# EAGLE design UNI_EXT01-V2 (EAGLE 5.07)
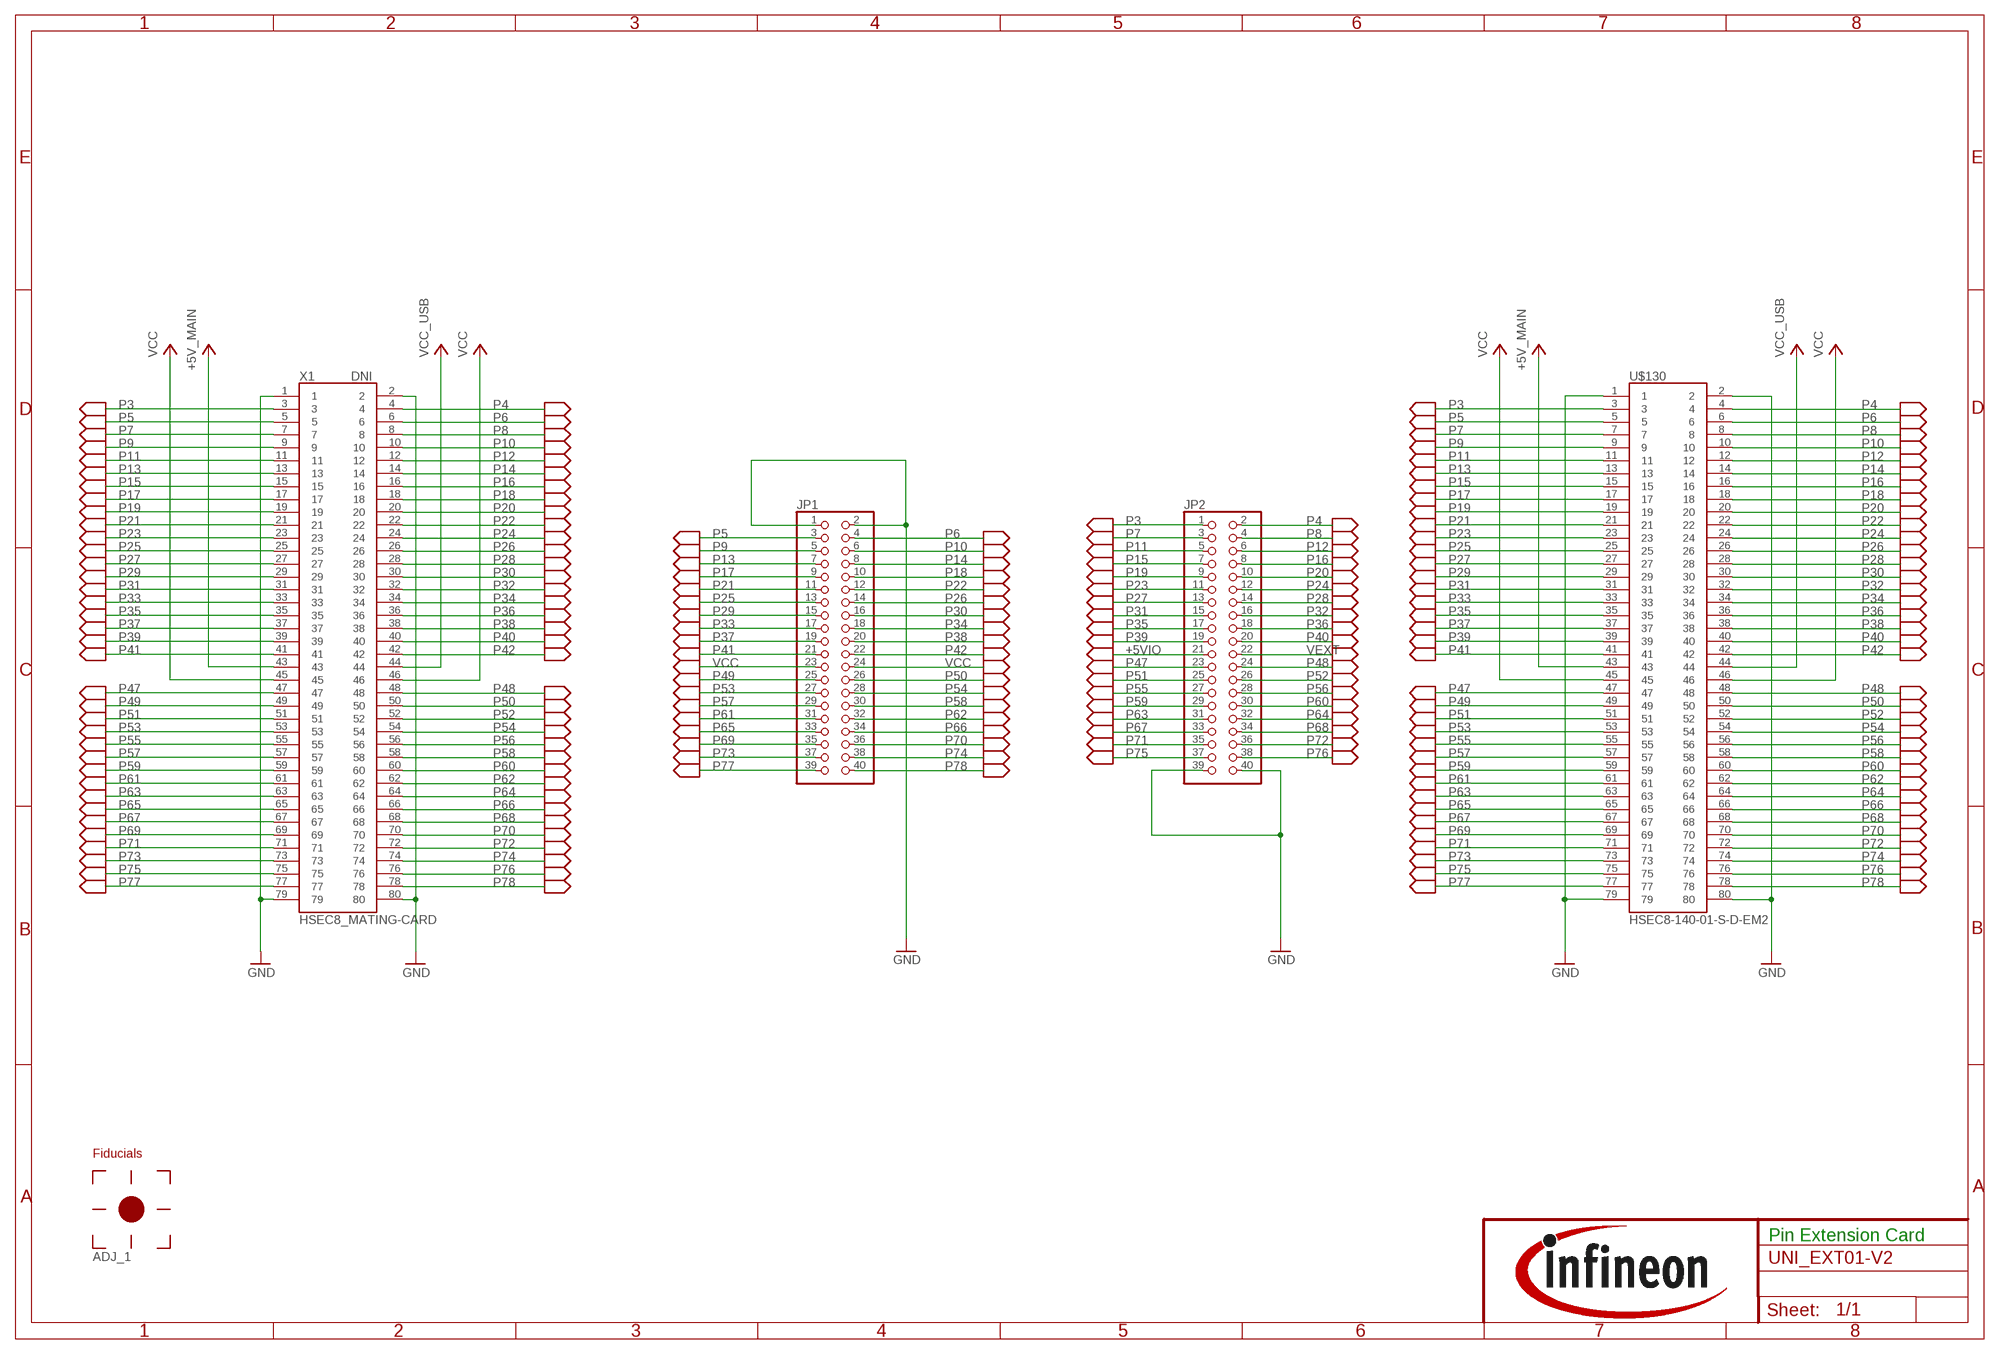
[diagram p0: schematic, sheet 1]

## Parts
ADJ_1  FIDUCIAL  [FIDUCIAL]
JP1  PINHD-2X20  [2X20]
JP2  PINHD-2X20  [2X20]
U$130  HSEC8-140-01-S-D-EM2  [HSEC8-140-01-XX-D-EM2]
X1  HSEC8_MATING-CARD  [HSEC8_MATING-CARD_80]

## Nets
+5VIO: JP2.21 U$130.43 X1.43 ; supply symbol labelled +5V_MAIN
GND: JP1.1 JP1.2 JP2.39 JP2.40 U$130.1 U$130.2 U$130.79 U$130.80 X1.1 X1.2 X1.79 X1.80
P3: JP2.1 U$130.3 X1.3
P4: JP2.2 U$130.4 X1.4
P5: JP1.3 U$130.5 X1.5
P6: JP1.4 U$130.6 X1.6
P7: JP2.3 U$130.7 X1.7
P8: JP2.4 U$130.8 X1.8
P9: JP1.5 U$130.9 X1.9
P10: JP1.6 U$130.10 X1.10
P11: JP2.5 U$130.11 X1.11
P12: JP2.6 U$130.12 X1.12
P13: JP1.7 U$130.13 X1.13
P14: JP1.8 U$130.14 X1.14
P15: JP2.7 U$130.15 X1.15
P16: JP2.8 U$130.16 X1.16
P17: JP1.9 U$130.17 X1.17
P18: JP1.10 U$130.18 X1.18
P19: JP2.9 U$130.19 X1.19
P20: JP2.10 U$130.20 X1.20
P21: JP1.11 U$130.21 X1.21
P22: JP1.12 U$130.22 X1.22
P23: JP2.11 U$130.23 X1.23
P24: JP2.12 U$130.24 X1.24
P25: JP1.13 U$130.25 X1.25
P26: JP1.14 U$130.26 X1.26
P27: JP2.13 U$130.27 X1.27
P28: JP2.14 U$130.28 X1.28
P29: JP1.15 U$130.29 X1.29
P30: JP1.16 U$130.30 X1.30
P31: JP2.15 U$130.31 X1.31
P32: JP2.16 U$130.32 X1.32
P33: JP1.17 U$130.33 X1.33
P34: JP1.18 U$130.34 X1.34
P35: JP2.17 U$130.35 X1.35
P36: JP2.18 U$130.36 X1.36
P37: JP1.19 U$130.37 X1.37
P38: JP1.20 U$130.38 X1.38
P39: JP2.19 U$130.39 X1.39
P40: JP2.20 U$130.40 X1.40
P41: JP1.21 U$130.41 X1.41
P42: JP1.22 U$130.42 X1.42
P47: JP2.23 U$130.47 X1.47
P48: JP2.24 U$130.48 X1.48
P49: JP1.25 U$130.49 X1.49
P50: JP1.26 U$130.50 X1.50
P51: JP2.25 U$130.51 X1.51
P52: JP2.26 U$130.52 X1.52
P53: JP1.27 U$130.53 X1.53
P54: JP1.28 U$130.54 X1.54
P55: JP2.27 U$130.55 X1.55
P56: JP2.28 U$130.56 X1.56
P57: JP1.29 U$130.57 X1.57
P58: JP1.30 U$130.58 X1.58
P59: JP2.29 U$130.59 X1.59
P60: JP2.30 U$130.60 X1.60
P61: JP1.31 U$130.61 X1.61
P62: JP1.32 U$130.62 X1.62
P63: JP2.31 U$130.63 X1.63
P64: JP2.32 U$130.64 X1.64
P65: JP1.33 U$130.65 X1.65
P66: JP1.34 U$130.66 X1.66
P67: JP2.33 U$130.67 X1.67
P68: JP2.34 U$130.68 X1.68
P69: JP1.35 U$130.69 X1.69
P70: JP1.36 U$130.70 X1.70
P71: JP2.35 U$130.71 X1.71
P72: JP2.36 U$130.72 X1.72
P73: JP1.37 U$130.73 X1.73
P74: JP1.38 U$130.74 X1.74
P75: JP2.37 U$130.75 X1.75
P76: JP2.38 U$130.76 X1.76
P77: JP1.39 U$130.77 X1.77
P78: JP1.40 U$130.78 X1.78
VCC: JP1.23 JP1.24 U$130.45 U$130.46 X1.45 X1.46
VEXT: JP2.22 U$130.44 X1.44 ; supply symbol labelled VCC_USB

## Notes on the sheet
- DNI
- Fiducials
- Pin Extension Card

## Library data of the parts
ADJ_1 = Global:FIDUCIAL: Fiducial
JP1 JP2 = pinhead:PINHD-2X20: PIN HEADER
U$130 = _HSEC8-140-01-XX-D-EM2:HSEC8-140-01-S-D-EM2
X1 = _XSE080:HSEC8_MATING-CARD

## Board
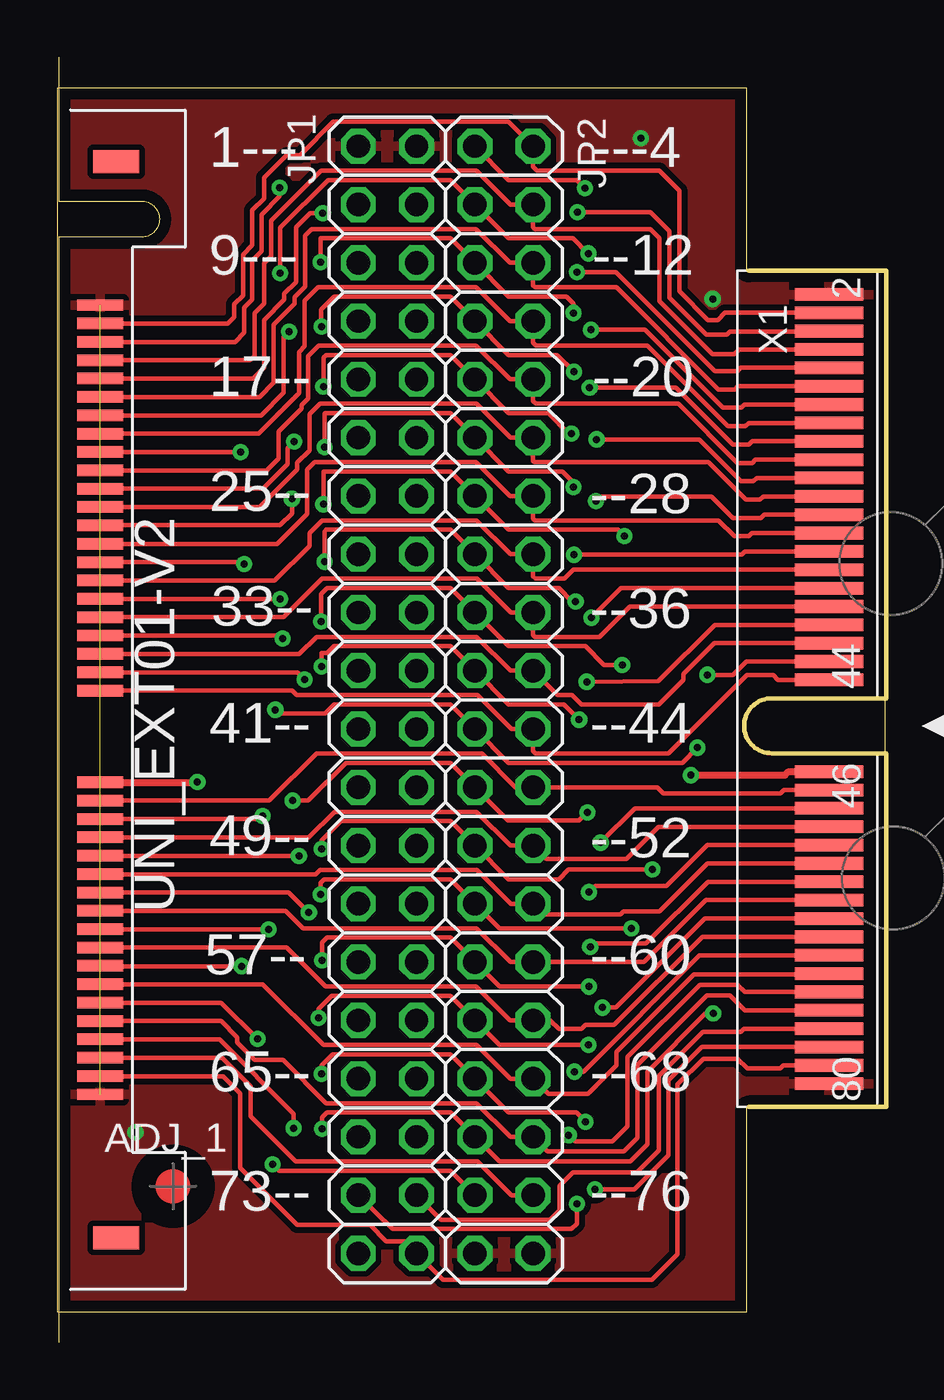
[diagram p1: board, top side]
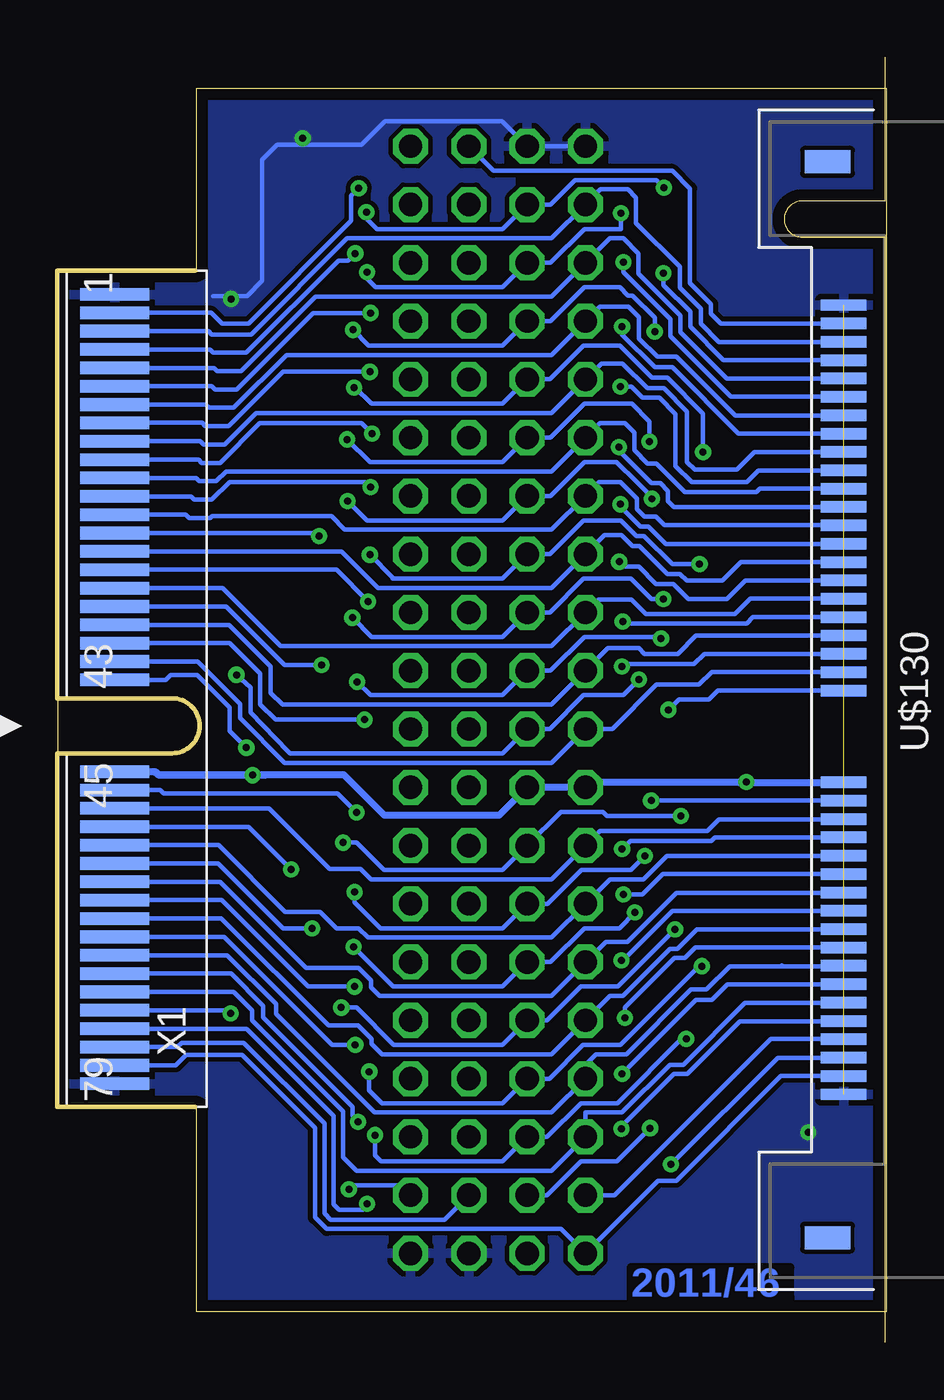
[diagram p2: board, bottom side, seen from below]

Size 36.14 x 56 mm. Coordinates in mm from the lower left corner, seen from the top.
Outline: 0,1.32 30.06,1.32 30.06,10.21 36.1,10.19 36.1,46.69 30.06,46.71 30.06,54.66 0,54.66 0,1.32
Copper layers (1+2*15+16): Top 0.035mm / dielectric 0.5mm / Route2 0.035mm / dielectric 0.5mm / Route15 0.035mm / dielectric 0.5mm / Bottom 0.035mm
Design rules "TESTCPU_01-A1 *": minimum track width 0.2mm, minimum drill 0.2mm, track to track 0.2mm, track to pad 0.2mm, pad to pad 0.15mm, via to via 0.2mm, smd to smd 0.2mm, copper to edge 0.5mm, drill to drill 0.5mm, minimum pad ring 10mil, minimum via ring 0.2mm, stop-mask expansion 4mil, vias tented up to drill 0.34mm, thermal gap 10mil

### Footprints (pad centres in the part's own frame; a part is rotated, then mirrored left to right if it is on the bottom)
2X20 = drill 1.016 octagon: 1 -24.13,-1.27; 2 -24.13,1.27; 3 -21.59,-1.27; 4 -21.59,1.27; 5 -19.05,-1.27; 6 -19.05,1.27; 7 -16.51,-1.27; 8 -16.51,1.27; 9 -13.97,-1.27; 10 -13.97,1.27; 11 -11.43,-1.27; 12 -11.43,1.27; 13 -8.89,-1.27; 14 -8.89,1.27; 15 -6.35,-1.27; 16 -6.35,1.27; 17 -3.81,-1.27; 18 -3.81,1.27; 19 -1.27,-1.27; 20 -1.27,1.27; 21 1.27,-1.27; 22 1.27,1.27; 23 3.81,-1.27; 24 3.81,1.27; 25 6.35,-1.27; 26 6.35,1.27; 27 8.89,-1.27; 28 8.89,1.27; 29 11.43,-1.27; 30 11.43,1.27; 31 13.97,-1.27; 32 13.97,1.27; 33 16.51,-1.27; 34 16.51,1.27; 35 19.05,-1.27; 36 19.05,1.27; 37 21.59,-1.27; 38 21.59,1.27; 39 24.13,-1.27; 40 24.13,1.27
HSEC8-140-01-XX-D-EM2 = smd 0.5 x 2: 1 -17.2,-1.8; 3 -16.4,-1.8; 5 -15.6,-1.8; 7 -14.8,-1.8; 9 -14,-1.8; 11 -13.2,-1.8; 13 -12.4,-1.8; 15 -11.6,-1.8; 17 -10.8,-1.8; 19 -10,-1.8; 21 -9.2,-1.8; 23 -8.4,-1.8; 25 -7.6,-1.8; 27 -6.8,-1.8; 29 -6,-1.8; 31 -5.2,-1.8; 33 -4.4,-1.8; 35 -3.6,-1.8; 37 -2.8,-1.8; 39 -2,-1.8; 41 -1.2,-1.8; 43 -0.4,-1.8; 45 3.6,-1.8; 47 4.4,-1.8; 49 5.2,-1.8; 51 6,-1.8; 53 6.8,-1.8; 55 7.6,-1.8; 57 8.4,-1.8; 59 9.2,-1.8; 61 10,-1.8; 63 10.8,-1.8; 65 11.6,-1.8; 67 12.4,-1.8; 69 13.2,-1.8; 71 14,-1.8; 73 14.8,-1.8; 75 15.6,-1.8; 77 16.4,-1.8; 79 17.2,-1.8 | smd 0.5 x 2 bottom: 2 -17.2,-1.8; 4 -16.4,-1.8; 6 -15.6,-1.8; 8 -14.8,-1.8; 10 -14,-1.8; 12 -13.2,-1.8; 14 -12.4,-1.8; 16 -11.6,-1.8; 18 -10.8,-1.8; 20 -10,-1.8; 22 -9.2,-1.8; 24 -8.4,-1.8; 26 -7.6,-1.8; 28 -6.8,-1.8; 30 -6,-1.8; 32 -5.2,-1.8; 34 -4.4,-1.8; 36 -3.6,-1.8; 38 -2.8,-1.8; 40 -2,-1.8; 42 -1.2,-1.8; 44 -0.4,-1.8; 46 3.6,-1.8; 48 4.4,-1.8; 50 5.2,-1.8; 52 6,-1.8; 54 6.8,-1.8; 56 7.6,-1.8; 58 8.4,-1.8; 60 9.2,-1.8; 62 10,-1.8; 64 10.8,-1.8; 66 11.6,-1.8; 68 12.4,-1.8; 70 13.2,-1.8; 72 14,-1.8; 74 14.8,-1.8; 76 15.6,-1.8; 78 16.4,-1.8; 80 17.2,-1.8 | smd 1 x 2: 81 -23.45,-2.5; 82 23.45,-2.5 | smd 1 x 2 bottom: 83 -23.45,-2.5; 84 23.45,-2.5
HSEC8_MATING-CARD_80 = smd 0.55 x 3 bottom: 1 -18.8,-2.5; 3 -18,-2.5; 5 -17.2,-2.5; 7 -16.4,-2.5; 9 -15.6,-2.5; 11 -14.8,-2.5; 13 -14,-2.5; 15 -13.2,-2.5; 17 -12.4,-2.5; 19 -11.6,-2.5; 21 -10.8,-2.5; 23 -10,-2.5; 25 -9.2,-2.5; 27 -8.4,-2.5; 29 -7.6,-2.5; 31 -6.8,-2.5; 33 -6,-2.5; 35 -5.2,-2.5; 37 -4.4,-2.5; 39 -3.6,-2.5; 41 -2.8,-2.5; 43 -2,-2.5; 45 2,-2.5; 47 2.8,-2.5; 49 3.6,-2.5; 51 4.4,-2.5; 53 5.2,-2.5; 55 6,-2.5; 57 6.8,-2.5; 59 7.6,-2.5; 61 8.4,-2.5; 63 9.2,-2.5; 65 10,-2.5; 67 10.8,-2.5; 69 11.6,-2.5; 71 12.4,-2.5; 73 13.2,-2.5; 75 14,-2.5; 77 14.8,-2.5; 79 15.6,-2.5 | smd 0.55 x 3: 2 -18.8,-2.5; 4 -18,-2.5; 6 -17.2,-2.5; 8 -16.4,-2.5; 10 -15.6,-2.5; 12 -14.8,-2.5; 14 -14,-2.5; 16 -13.2,-2.5; 18 -12.4,-2.5; 20 -11.6,-2.5; 22 -10.8,-2.5; 24 -10,-2.5; 26 -9.2,-2.5; 28 -8.4,-2.5; 30 -7.6,-2.5; 32 -6.8,-2.5; 34 -6,-2.5; 36 -5.2,-2.5; 38 -4.4,-2.5; 40 -3.6,-2.5; 42 -2.8,-2.5; 44 -2,-2.5; 46 2,-2.5; 48 2.8,-2.5; 50 3.6,-2.5; 52 4.4,-2.5; 54 5.2,-2.5; 56 6,-2.5; 58 6.8,-2.5; 60 7.6,-2.5; 62 8.4,-2.5; 64 9.2,-2.5; 66 10,-2.5; 68 10.8,-2.5; 70 11.6,-2.5; 72 12.4,-2.5; 74 13.2,-2.5; 76 14,-2.5; 78 14.8,-2.5; 80 15.6,-2.5

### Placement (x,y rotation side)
ADJ_1  5.05,6.79 0 top
JP1  14.39,27.99 270 top
JP2  19.47,27.99 270 top
U$130  0.06,28 270 bottom
X1  36.14,26.86 270 top

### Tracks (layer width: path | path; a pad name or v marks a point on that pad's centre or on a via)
+5VIO  (via drill 0.3)
  Top 0.203: v27.9,25.91 27.24,25.25 19.67,25.25 JP2.21 17.13,27.79 12.05,27.79 11.67,27.41 9.65,27.41 v9.5,27.56
  Bottom 0.203: v27.9,25.91 28.64,26.65 28.64,27.66 30.05,29.07 31.21,29.07 31.42,28.86 X1.43 | v9.5,27.56 9.05,28.02 7.73,28.02 7.35,28.4 U$130.43
GND  (via drill 0.3)  (1 unrouted)
  Bottom 0.203: JP1.1 JP1.2 16.75,53.22 21.86,53.22 22.87,52.2 26.56,52.2 27.22,51.54 27.22,46.26 27.88,45.6 29.35,45.6
  other vias: 25.44,52.48 28.57,45.47 3.4,9.14
  pour Bottom: 0.31,54.66 30.06,54.66 30.06,47.04 35.98,47.04 35.98,10.21 29.96,10.11 29.96,1.22 0.31,1.32
  pour Top (isolate 0.254): 0.51,54.61 29.93,54.71 29.93,46.69 35.9,46.59 35.9,10.21 30.05,9.81 30.05,1.18 0.51,1.58
P3  (via drill 0.3)
  Top 0.203: JP2.1 19.67,50.65 22.64,50.65 v23,50.3
  Bottom 0.203: JP2.1 17.13,51.06 9.33,51.06 8.56,50.28 8.56,46.16 7.64,45.25 7.64,44.83 7.21,44.4 U$130.3 | v23,50.3 23.33,49.97 23.33,48.87 27.8,44.4 28.97,44.4 29.43,44.86 X1.3
P4
  Top 0.203: X1.4 29.1,44.86 28.79,44.56 28.36,44.56 27.11,45.8 27.11,50.19 26.25,51.06 20.92,51.06 20.74,51.24 JP2.2 19.67,53.19 12.03,53.19 10.58,51.74 10,51.74 9.01,50.75 9.01,49.84 8.5,49.33 8.5,47.81 8.09,47.4 8.09,45.62 7.71,45.24 7.71,44.68 7.42,44.39 U$130.4
  Top 0.254: U$130.4
P5
  Bottom 0.203: X1.5 29.55,44.07 29.4,43.92 27.7,43.92 23.51,48.11 14.59,48.11 JP1.3 12.46,50.24 11.27,50.24 10.91,49.89 10.91,48.77 9.01,46.87 9.01,45.95 8.09,45.04 8.1,45.03 8.1,44.39 7.29,43.59 1.87,43.59 U$130.5
P6  (via drill 0.3)
  Top 0.203: v9.69,50.32 9.69,49.94 8.9,49.15 8.9,47.55 8.5,47.15 8.5,45.44 8.14,45.09 8.14,44 7.74,43.59 U$130.6 | v22.67,49.25 25.84,49.25 26.68,48.42 26.68,45.52 28.28,43.92 29.18,43.92 29.31,44.05 X1.6
  Bottom 0.203: v9.69,50.32 10.02,50.65 13.58,50.65 14.64,49.58 JP1.4 16.73,48.52 22.21,48.52 22.67,48.97 v22.67,49.25
P7  (via drill 0.3)
  Top 0.203: v9.72,46.59 9.72,48.57 11.8,50.65 17.13,50.65 JP2.3 19.67,48.11 22.47,48.11 23.13,47.45 v23.15,47.45
  Bottom 0.203: v9.72,46.59 9.72,46.08 8.55,44.91 8.55,44.25 7.09,42.8 U$130.7 | v23.15,47.45 23.46,47.15 23.89,47.15 27.91,43.12 29.35,43.12 29.49,43.26 X1.7 | X1.7
P8
  Top 0.203: X1.8 29.72,43.27 29.51,43.06 28.56,43.06 26.25,45.37 26.25,48.11 25.84,48.52 20.82,48.52 20.74,48.59 JP2.4 19.75,49.58 18.28,51.06 11.49,51.06 9.31,48.87 9.31,47.32 9.01,47.02 9.01,45.27 8.6,44.86 8.6,42.98 8.41,42.79 U$130.8
P9
  Bottom 0.203: X1.9 29.3,42.46 29.17,42.32 28.13,42.32 24.88,45.57 14.59,45.57 JP1.5 12.05,48.11 11.47,48.11 10.81,47.45 10.81,46.56 8.98,44.73 8.99,44.73 8.99,44.02 6.95,41.99 1.87,41.99 U$130.9
P10  (via drill 0.3)
  Top 0.203: v11.57,49.2 11.01,49.2 10.4,48.59 10.4,46.21 9.89,45.7 9.89,45.44 9.01,44.56 9.01,42.47 8.53,41.99 U$130.10 | v22.64,46.64 24.35,46.64 28.66,42.32 29.64,42.32 29.79,42.47 X1.10
  Bottom 0.203: v11.57,49.2 11.57,48.52 13.17,48.52 14.64,47.04 JP1.6 16.73,45.98 22.26,45.98 22.64,46.36 v22.64,46.64
P11  (via drill 0.3)
  Top 0.203: v11.47,47.07 11.47,48.11 17.13,48.11 JP2.5 19.67,45.57 22.19,45.57 22.49,45.27 v22.49,44.86
  Bottom 0.203: v11.47,47.07 11.47,46.64 9.41,44.58 9.41,43.84 6.78,41.21 1.88,41.21 U$130.11 | v22.49,44.86 24.98,44.86 28.32,41.52 29.27,41.52 29.41,41.67 X1.11
P12
  Top 0.203: X1.12 29.67,41.66 29.53,41.52 28.82,41.52 24.37,45.98 20.82,45.98 20.74,46.05 JP2.6 19.72,47.04 18.25,48.52 11.09,48.52 10.81,48.24 10.81,46 10.35,45.55 10.35,45.27 9.44,44.35 9.44,41.81 8.82,41.19 U$130.12
P13
  Bottom 0.203: X1.13 29.67,40.86 29.53,40.72 28.46,40.72 26.15,43.03 14.59,43.03 JP1.7 12.49,45.14 11.24,45.14 10.78,44.68 10.78,43.75 9.98,42.95 9.15,42.95 6.59,40.39 1.87,40.39 U$130.13
P14  (via drill 0.3)
  Top 0.203: v10.1,44.05 9.87,43.82 9.87,41.38 8.88,40.39 U$130.14 | v23.25,44.12 25.62,44.12 29.02,40.72 29.82,40.72 29.96,40.86 X1.14
  Bottom 0.203: v10.1,44.05 10.1,44.66 11.06,45.62 11.27,45.62 11.62,45.98 13.17,45.98 14.64,44.5 JP1.8 16.73,43.44 22.57,43.44 v23.25,44.12
P15  (via drill 0.3)
  Top 0.203: v22.52,42.29 21.78,43.03 19.67,43.03 JP2.7 17.13,45.57 12.05,45.57 11.49,45.01 11.49,44.29 v11.52,44.27
  Bottom 0.203: v22.52,42.29 26.3,42.29 28.67,39.92 29.69,39.92 29.84,40.07 X1.15 | v11.52,44.27 11.52,43.92 10.09,42.49 9.33,42.49 6.44,39.6 U$130.15
P16
  Top 0.203: X1.16 30.14,40.06 30,39.92 29.23,39.92 25.72,43.44 20.87,43.44 20.74,43.56 JP2.8 19.72,44.5 18.25,45.98 11.37,45.98 10.78,45.39 10.78,43.41 10.53,43.16 10.53,41.35 8.77,39.59 U$130.16
P17
  Bottom 0.203: X1.17 29.91,39.26 29.77,39.12 28.84,39.12 27.47,40.49 14.59,40.49 JP1.9 12.43,42.66 11.51,42.66 10.43,41.57 9.7,41.57 8.69,40.56 8.69,38.37 8.35,38.03 6.52,38.03 5.75,38.8 2.63,38.8 2.59,38.77 1.9,38.77 U$130.17
P18  (via drill 0.3)
  Top 0.203: v7.98,38.79 v7.99,38.79 1.86,38.79 U$130.18 | v23.2,41.61 26.96,41.61 29.45,39.12 30.15,39.12 30.29,39.26 X1.18
  Bottom 0.203: v23.2,41.61 23.15,41.61 22.44,40.9 16.73,40.9 JP1.10 14.67,41.96 13.2,43.44 11.62,43.44 10.22,42.04 9.55,42.04 7.99,40.48 v7.99,38.79
P19  (via drill 0.3)
  Top 0.203: v11.6,41.64 11.6,42.9 11.72,43.03 17.13,43.03 JP2.9 19.67,40.49 21.4,40.49 22.29,39.6 v22.42,39.6
  Bottom 0.203: v22.42,39.6 22.87,40.06 27.32,40.06 29.05,38.32 29.85,38.32 29.99,38.46 X1.19 | v11.6,41.64 11.11,41.64 10.63,41.16 9.9,41.16 9.19,40.45 9.19,38.19 8.48,37.48 6.09,37.48 5.57,37.99 U$130.19
P20
  Top 0.203: X1.20 30.43,38.46 30.29,38.32 29.64,38.32 27.06,40.9 20.87,40.9 20.74,41.02 JP2.10 19.72,41.96 18.25,43.44 11.39,43.44 10.94,42.98 10.94,41.13 10.66,40.85 10.66,40.69 9.64,39.68 9.64,38.51 9.12,37.99 U$130.20
P21
  Bottom 0.203: X1.21 30.09,37.67 29.95,37.52 29.22,37.52 28.79,37.95 14.59,37.95 JP1.11 12.48,40.06 11.4,40.06 10.99,39.65 10.99,38.87 10.41,38.29 10.01,38.29 8.78,37.06 5.66,37.06 5.52,37.2 U$130.21
P22  (via drill 0.3)
  Top 0.203: v10.33,39.25 10.05,38.97 10.05,38.28 8.96,37.19 U$130.22 | v23.51,39.35 27.98,39.35 29.8,37.52 30.35,37.52 30.49,37.67 X1.22
  Bottom 0.203: v23.51,39.35 22.52,38.36 16.73,38.36 JP1.12 14.64,39.42 13.17,40.9 11.1,40.9 10.33,40.13 v10.33,39.25
P23  (via drill 0.3)
  Top 0.203: v11.65,39.01 11.65,40.47 11.67,40.49 17.13,40.49 JP2.11 19.67,37.95 22.01,37.95 22.49,37.47 v22.49,37.27
  Bottom 0.203: v22.49,37.27 22.72,37.49 28.64,37.49 29.41,36.72 30.17,36.72 30.31,36.86 X1.23 | v11.65,39.01 11.65,38.85 10.25,37.44 9.85,37.44 9.52,37.11 9.52,36.66 9.26,36.4 U$130.23
P24
  Top 0.203: X1.24 30.77,36.86 30.63,36.72 30.02,36.72 28.38,38.36 20.79,38.36 20.74,38.41 JP2.12 19.75,39.42 18.28,40.9 11.44,40.9 10.99,40.44 10.99,38.87 10.45,38.33 10.45,38.03 8.82,36.39 U$130.24
P25
  Bottom 0.203: X1.25 30.55,36.07 30.4,35.92 29.48,35.92 29.4,36 24.19,36 23.61,35.41 14.59,35.41 JP1.13 12.52,37.48 11.6,37.48 10.88,36.77 10.88,36.31 10.55,35.98 10.05,35.98 9.69,35.61 U$130.25
P26  (via drill 0.3)
  Top 0.203: v10.22,36.76 10.22,36.12 9.72,35.61 U$130.26 | v23.48,36.66 23.69,36.86 28.51,36.86 29.45,35.92 30.68,35.92 30.82,36.06 X1.26
  Bottom 0.203: v10.22,36.76 10.22,36.83 10.88,37.49 11.77,38.36 13.17,38.36 14.64,36.88 JP1.14 16.73,35.82 22.64,35.82 v23.48,36.66
P27  (via drill 0.3)
  Top 0.203: v11.6,36.52 11.6,37.95 17.13,37.95 JP2.13 19.67,35.41 24.45,35.41 v24.73,35.13
  Bottom 0.203: v24.73,35.13 24.86,35.26 X1.27 | v11.6,36.52 11.6,36.43 10.73,35.56 10.37,35.56 9.6,34.79 U$130.27
P28
  Top 0.203: X1.28 30.28,35.26 30.14,35.12 29.51,35.12 28.82,35.82 20.82,35.82 20.74,35.89 JP2.14 19.72,36.88 18.25,38.36 11.21,38.36 10.88,38.03 10.88,36.1 9.58,34.79 U$130.28
P29
  Bottom 0.203: X1.29 23.76,34.46 22.16,32.87 14.59,32.87 JP1.15 12.29,35.17 11.55,35.17 11.08,34.69 10.76,34.69 9.55,33.48 9,33.48 8.71,33.19 7.14,33.19 6.35,33.99 1.87,33.99 U$130.29 1.86,33.99
P30  (via drill 0.3)
  Top 0.203: v8.14,33.91 8.06,33.99 U$130.30 | X1.30 29.98,34.46 29.83,34.32 v22.52,34.32
  Bottom 0.203: v8.14,33.91 9.34,33.91 9.34,33.92 10.56,35.14 10.9,35.14 11.57,35.82 13.2,35.82 14.67,34.34 JP1.16 16.73,33.28 21.53,33.28 21.53,33.33 v22.52,34.32
P31  (via drill 0.3)
  Top 0.203: v11.65,34.01 11.65,35.34 11.72,35.41 17.13,35.41 JP2.15 19.67,32.87 21.86,32.87 22.44,32.29 v22.59,32.29
  Bottom 0.203: v22.59,32.29 23.97,33.66 X1.31 | v11.65,34.01 11.43,33.8 10.79,33.8 10.04,33.05 9.29,33.05 8.63,32.39 6.95,32.39 6.14,33.19 1.87,33.19 U$130.31
P32
  Top 0.203: X1.32 22.5,33.66 22.11,33.28 20.84,33.28 20.74,33.38 JP2.16 19.75,34.34 18.28,35.82 11.54,35.82 10.99,35.26 10.99,34.7 9.48,33.19 U$130.32
P33
  Bottom 0.203: X1.33 28.94,32.86 26.4,30.33 14.59,30.33 JP1.17 12.56,32.37 11.11,32.37 10.47,31.73 6.6,31.73 5.94,32.4 U$130.33
P34  (via drill 0.3)
  Top 0.203: v23.28,31.58 24.57,32.86 X1.34 | v9.72,32.39 1.86,32.39 U$130.34
  Bottom 0.203: v9.72,32.39 10.25,32.39 11.14,33.28 13.2,33.28 14.67,31.8 JP1.18 16.73,30.74 22.44,30.74 v23.28,31.58
P35  (via drill 0.3)
  Top 0.203: v11.49,31.41 11.49,32.62 11.75,32.87 17.13,32.87 JP2.17 19.67,30.33 23.03,30.33 23.84,29.52 v24.63,29.52
  Bottom 0.203: v24.63,29.52 26.23,29.52 28.77,32.06 X1.35 | v11.49,31.41 11.41,31.33 6.09,31.33 5.82,31.6 U$130.35
P36
  Top 0.203: X1.36 24.96,32.06 23.64,30.74 20.82,30.74 20.74,30.81 JP2.18 19.77,31.8 18.3,33.28 11.54,33.28 9.86,31.59 U$130.36
P37
  Bottom 0.203: X1.37 28.66,31.26 26.84,29.44 26.84,28.3 26.33,27.79 14.59,27.79 JP1.19 12.13,30.25 10.8,30.25 10.54,30 9.1,30 8.29,30.8 U$130.37
P38  (via drill 0.3)
  Top 0.203: 9.81,30.79 v9.82,30.66 9.82,30.8 U$130.38 | v23.08,28.78 26.2,28.81 28.66,31.26 X1.38
  Bottom 0.203: v9.82,30.66 9.82,30.74 13.17,30.74 14.64,29.26 JP1.20 16.73,28.2 22.49,28.2 v23.08,28.78
P39  (via drill 0.3)
  Top 0.203: v22.75,27.13 22.09,27.79 19.67,27.79 JP2.19 17.13,30.33 12.05,30.33 11.75,30.03 11.53,30.03 v11.53,29.44
  Bottom 0.203: v22.75,27.13 26.63,27.13 27.29,27.79 27.29,29.14 28.62,30.46 X1.39 | v11.53,29.44 11.42,29.55 8.39,29.55 7.93,30 U$130.39
P40
  Top 0.203: X1.40 28.65,30.46 27.29,29.11 27.29,28.86 26.23,27.79 22.85,27.79 22.44,28.2 21.81,28.2 JP2.20 19.75,29.26 18.28,30.74 11.29,30.74 10.55,29.99 U$130.40
P41
  Bottom 0.203: X1.41 30.03,29.66 28.18,27.82 28.18,27.21 26.23,25.25 14.59,25.25 JP1.21 11.95,26.72 10.02,28.65 8.17,28.65 7.61,29.21 U$130.41
P42  (via drill 0.3)
  Top 0.203: v10.78,28.88 10.47,29.19 U$130.42 | v28.33,29.09 29.45,29.09 30.03,29.66 X1.42
  Bottom 0.203: v10.78,28.88 11.47,28.2 13.2,28.2 14.67,26.72 JP1.22 16.73,25.66 26,25.66 26.07,25.73 27.72,27.44 27.72,28.53 v28.33,29.09
P47  (via drill 0.3)
  Top 0.203: v23.1,23.09 22.75,22.74 19.65,22.74 JP2.23 17.13,25.25 12.59,25.25 10.94,23.6 v10.25,23.6
  Bottom 0.203: v23.1,23.09 23.93,23.92 31.51,23.92 31.66,24.07 X1.47 | v10.25,23.6 U$130.47
P48
  Top 0.203: X1.48 31.67,24.07 31.53,23.92 26.41,23.92 26.15,24.18 JP2.24 19.98,24.18 18.5,25.66 11.29,25.66 9.23,23.6 U$130.48
P49
  Bottom 0.203: X1.49 26.91,23.26 24.27,20.63 22.92,20.63 22.47,20.17 14.59,20.17 JP1.25 12.49,22.28 7.81,22.28 7.3,22.79 1.86,22.79 U$130.49
P50  (via drill 0.3)
  Top 0.203: v8.95,22.94 8.81,22.79 U$130.50 | v23.69,21.77 25.18,23.26 X1.50
  Bottom 0.203: v8.95,22.94 12.18,22.94 12.36,23.12 14.19,23.12 JP1.26 16.73,20.58 21.91,20.58 23.1,21.77 v23.69,21.77
P51  (via drill 0.3)
  Top 0.203: v11.52,21.49 11.52,21.87 12.36,22.71 17.13,22.71 JP2.25 19.67,20.17 21.86,20.17 22.29,20.6 v25.95,20.6
  Bottom 0.203: v11.52,21.49 11.16,21.85 7.63,21.85 7.48,22 U$130.51 | v25.95,20.6 27.81,22.46 X1.51
P52
  Top 0.203: X1.52 26.21,22.46 24.8,21.06 21.32,21.06 JP2.26 19.75,21.64 18.28,23.12 12.08,23.12 10.96,21.99 U$130.52
P53
  Bottom 0.203: X1.53 29.12,21.66 26.2,18.75 24.68,18.75 23.97,18.04 23,18.04 22.59,17.63 14.59,17.63 JP1.27 12.05,20.17 10.58,20.17 9.56,21.19 1.86,21.19 U$130.53
P54  (via drill 0.3)
  Top 0.203: v23.18,19.61 23.46,19.89 26.56,19.89 28.33,21.66 X1.54 | v10.53,21.19 1.86,21.19 U$130.54
  Bottom 0.203: v10.53,21.19 11.14,20.58 13.3,20.58 14.77,19.1 JP1.28 16.73,18.04 22.06,18.04 23.18,19.16 v23.18,19.61
P55  (via drill 0.3)
  Top 0.203: v11.47,19.51 11.47,20.02 11.62,20.17 17.13,20.17 JP2.27 19.27,18.04 v25.03,18.04
  Bottom 0.203: v11.47,19.51 10.63,19.51 9.74,20.4 U$130.55 | v25.03,18.04 26.3,18.04 29.13,20.86 X1.55 | U$130.55
P56
  Top 0.203: X1.56 28.34,20.86 26.25,18.77 24.68,18.77 24.55,18.65 21.2,18.65 JP2.28 19.77,19.1 18.3,20.58 11.44,20.58 11.26,20.39 U$130.56
P57
  Bottom 0.203: X1.57 29.04,20.06 25.29,16.31 23,16.31 22.47,15.78 22.47,15.47 22.09,15.09 14.59,15.09 JP1.29 12.23,17.45 11.29,17.45 9.16,19.59 1.86,19.59 U$130.57
P58  (via drill 0.3)
  Top 0.203: v10.96,18.72 10.09,19.59 U$130.58 | v23.23,17.22 23.38,17.38 25.67,17.38 28.36,20.06 X1.58
  Bottom 0.203: v10.96,18.72 11.65,18.04 13.17,18.04 14.64,16.56 JP1.30 16.73,15.5 21.5,15.5 v23.23,17.22
P59  (via drill 0.3)
  Top 0.203: v11.54,16.64 11.54,17.43 11.75,17.63 17.13,17.63 JP2.29 19.27,15.5 v23.18,15.5
  Bottom 0.203: v11.54,16.64 11.49,16.64 9.34,18.8 U$130.59 | v23.18,15.5 25.21,15.5 28.98,19.26 X1.59 | U$130.59
P60
  Top 0.203: X1.60 28.27,19.26 25.57,16.56 JP2.30 19.75,16.56 18.28,18.04 10.71,18.04 9.95,18.8 U$130.60 | U$130.60
P61
  Bottom 0.203: X1.61 28.99,18.46 24.32,13.8 23.03,13.8 22.44,13.21 22.44,13.01 21.98,12.55 14.59,12.55 JP1.31 12.05,15.09 11.49,15.09 9.44,17.15 9.11,17.15 8.27,17.99 1.86,17.99 U$130.61
P62  (via drill 0.3)
  Top 0.203: v23.76,14.58 24.35,14.58 28.23,18.46 X1.62 | v9.21,17.99 1.86,17.99 U$130.62
  Bottom 0.203: v9.21,17.99 11.7,15.5 13.32,15.5 14.8,14.02 JP1.32 16.73,12.96 21.48,12.96 23.1,14.58 v23.76,14.58
P63  (via drill 0.3)
  Top 0.203: v11.39,14.13 11.39,14.53 11.95,15.09 17.13,15.09 JP2.31 19.27,12.96 v23.15,12.96
  Bottom 0.203: v11.39,14.13 11.39,14.58 9.23,16.74 8.78,16.74 8.32,17.2 U$130.63 | v23.15,12.96 24.17,12.96 28.88,17.66 X1.63 | U$130.63
P64
  Top 0.203: X1.64 28.11,17.66 24.27,13.82 23.03,13.82 22.85,13.64 21.86,13.64 21.48,14.02 JP2.32 19.72,14.02 18.25,15.5 11.7,15.5 10,17.19 U$130.64
P65
  Bottom 0.203: 4.58,16.39 6.82,16.39 7.84,15.37 8.52,15.37 11.34,12.55 12.66,12.55 13.12,12.09 JP1.33 14.59,10.01 22.31,10.01 26.61,14.3 26.61,14.74 28.74,16.86 X1.65 | 4.58,16.39 4.55,16.41 | 4.58,16.39 1.86,16.39 U$130.65
P66  (via drill 0.3)
  Top 0.203: v8.03,16.39 v8.04,16.39 1.86,16.39 U$130.66 | v22.54,11.79 22.92,11.79 28,16.86 X1.66
  Bottom 0.203: v8.04,16.39 8.17,16.39 11.6,12.96 13.22,12.96 14.7,11.48 JP1.34 16.73,10.42 21.98,10.42 22.54,10.98 v22.54,11.79
P67  (via drill 0.3)
  Top 0.203: v11.52,11.69 11.52,12.07 12,12.55 17.13,12.55 JP2.33 19.67,10.01 22.62,10.01 v23.03,9.6
  Bottom 0.203: v11.52,11.69 8.29,14.91 7.61,14.91 6.92,15.6 U$130.67 | v23.03,9.6 23.28,9.86 23.28,10.27 27.17,14.15 27.17,14.66 28.57,16.06 X1.67 | U$130.67
P68
  Top 0.203: X1.68 33.61,16.03 27.75,16.03 24.37,12.65 24.37,12.07 23.13,10.82 21.4,10.82 JP2.34 19.75,11.48 18.28,12.96 11.6,12.96 8.96,15.59 U$130.68
P69
  Bottom 0.203: X1.69 28.46,15.26 27.65,14.46 27.65,14.02 23.69,10.06 23.69,8.06 23.1,7.47 14.59,7.47 JP1.35 13.12,10.01 11.52,10.01 9.44,12.09 8.85,12.09 6.16,14.79 1.86,14.79 U$130.69
P70  (via drill 0.3)
  Top 0.203: v8.73,13.21 7.14,14.79 U$130.70 | v22.29,9.02 22.57,8.74 24.19,8.74 24.86,9.4 24.86,12.42 28,15.57 29.65,15.57 29.97,15.26 X1.70
  Bottom 0.203: v8.73,13.21 8.93,13.21 11.72,10.42 13.32,10.42 14.8,8.94 JP1.36 16.73,7.88 22.04,7.88 22.29,8.13 v22.29,9.02
P71  (via drill 0.3)
  Top 0.203: v11.54,9.3 11.54,9.81 11.75,10.01 17.13,10.01 JP2.35 19.27,7.88 24.98,7.88 25.72,8.61 25.72,11.79 28.26,14.33 v28.59,14.33 28.38,14.33
  Bottom 0.203: v11.54,9.3 11.54,9.4 9.26,11.69 8.68,11.69 6.39,13.97 1.86,13.97 U$130.71 | v28.59,14.32 v28.59,14.33 28.72,14.46 X1.71
P72
  Top 0.203: X1.72 29.98,14.46 29.32,15.12 28.31,15.12 25.29,12.09 25.29,8.89 24.7,8.31 21.38,8.31 JP2.36 19.75,8.94 18.28,10.42 11.72,10.42 9.84,12.3 8.6,12.3 7.84,13.06 7.84,13.29 7.13,13.99 U$130.72
P73  (via drill 0.3)
  Top 0.203: JP1.37 14.62,4.93 22.42,4.93 22.64,5.16 v22.64,6.02
  Bottom 0.203: JP1.37 11.85,6.4 5.04,13.21 U$130.73 | v22.64,6.02 22.82,5.77 23.86,5.77 24.09,6 24.09,9.86 27.9,13.66 X1.73
P74  (via drill 0.3)
  Top 0.203: v10.3,9.33 10.3,9.96 7.07,13.19 U$130.74 | JP1.38 16.73,5.34 21.48,5.34 21.88,5.74 21.88,6.81 22.47,7.4 25.26,7.4 26.23,8.36 26.23,11.61 28.14,13.52 29.8,13.52 29.94,13.66 X1.74
  Bottom 0.203: JP1.38 14.8,6.4 13.32,7.88 11.75,7.88 v10.3,9.33
P75  (via drill 0.3)
  Top 0.203: JP2.37 17.13,7.47 9.67,7.47 v9.39,7.75
  Bottom 0.203: v9.39,7.75 4.74,12.4 U$130.75 | JP2.37 19.27,5.34 24.22,5.34 24.5,5.62 24.5,9.53 28.02,13.05 30.73,13.05 30.92,12.86 X1.75
P76  (via drill 0.3)
  Top 0.203: JP2.38 19.8,6.4 18.33,7.88 10.38,7.88 8.42,9.83 8.42,11.15 7.18,12.39 U$130.76 | v23.43,6.66 25.16,6.66 26.63,8.13 26.63,11.41 28.09,12.86 X1.76
  Bottom 0.203: JP2.38 21.17,6.84 23.25,6.84 v23.43,6.66
P77
  Bottom 0.203: X1.77 30.98,12.07 30.52,12.53 28.08,12.53 24.91,9.35 24.91,5.44 24.4,4.93 14.19,4.93 JP1.39 9.95,7.03 9.16,7.03 4.59,11.6 U$130.77
P78
  Top 0.203: X1.78 31.65,12.06 31.51,11.92 30.08,11.92 29.65,12.35 28.16,12.35 27.04,11.23 27.04,3.84 25.92,2.72 16.8,2.72 JP1.40 15.13,4.4 14.34,4.4 13.63,5.11 10.45,5.11 7.96,7.6 7.96,10.85 7.22,11.59 U$130.78
VCC  (via drill 0.3)
  Top 0.305: X1.46 31.87,24.86 31.72,24.71 v27.62,24.71 | U$130.46 6.09,24.4 v6.1,24.41
  Bottom 0.305: 27.06,24.72 27.07,24.71 v27.62,24.71 31.71,24.71 31.86,24.86 X1.46 31.86,24.86 31.73,24.72 23.64,24.72 21.88,22.97 16.88,22.97 JP1.24 JP1.23 12.91,24.4 6.76,24.4 | 6.44,24.4 U$130.46 | 6.44,24.4 6.76,24.4 | 6.76,24.4 6.77,24.41 | v6.1,24.41 6.43,24.41 6.44,24.4
VEXT
  Top 0.203: X1.44 31.42,28.86 31.21,29.07 30.05,29.07 26.63,25.66 20.84,25.66 20.74,25.76 JP2.22 19.8,26.72 18.33,28.2 10.43,28.2 10.23,28.39 U$130.44

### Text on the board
Bottom: 2011/46
tTest: 1 | 4 | 77 | 80
tSilk: 1--- | ---4 | 9--- | --12 | 17-- | --20 | 25-- | --28 | 33-- | --36 | 41-- | --44 | 49-- | --52 | UNI_EXT01-V2 | 57-- | --60 | 65-- | --68 | 73-- | --76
